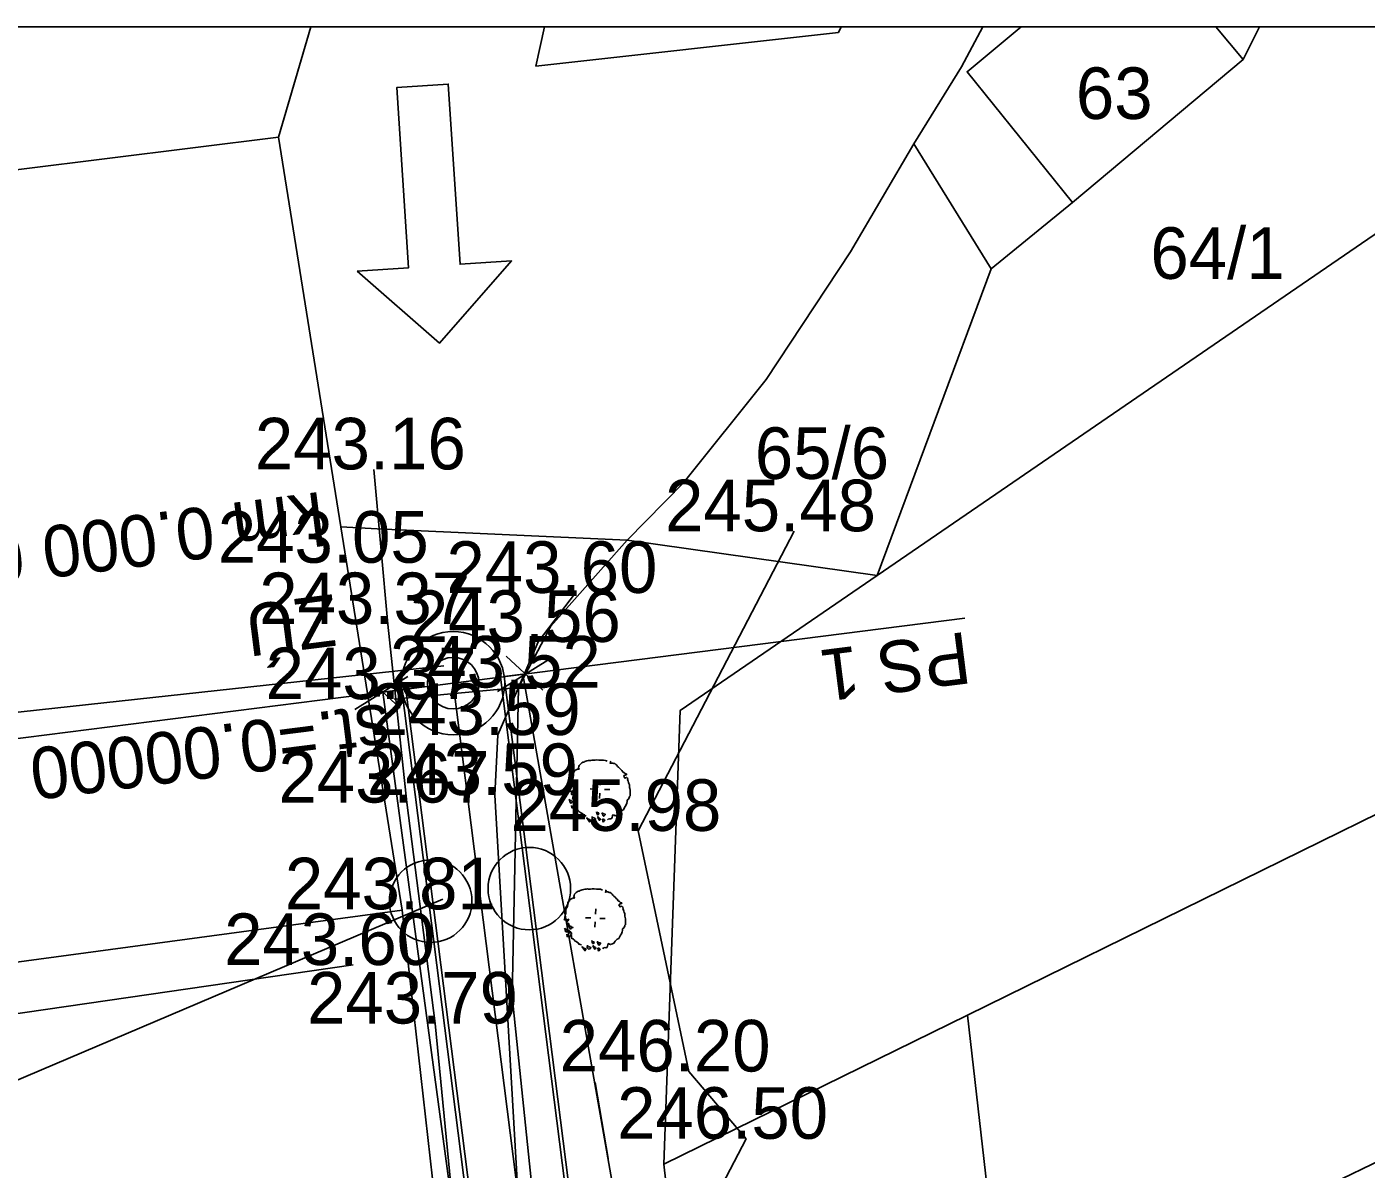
# Model space of a CAD drawing. Extents: x -601754 to -601440, y -1201912 to -1200862.
# Drawn here: x -601652.4 to -601600.5, y -1200906.7 to -1200862.4 of the extents above; entities that cross this region are included whole.
import ezdxf

# ---------------------------------------------------------------- set-up
doc = ezdxf.new("R2010")
doc.units = 0
for name, color, linetype in [('Hranice parcel', 7, 'Continuous'), ('Parcelní čísla', 7, 'Continuous'), ('u_hrany', 7, 'Continuous'), ('u_krizky', 7, 'Continuous'), ('u_návrh', 7, 'Continuous'), ('u_osa', 7, 'Continuous'), ('u_popis', 7, 'Continuous'), ('u_pricne_cesta', 7, 'Continuous'), ('u_prijezd', 7, 'Continuous'), ('u_S0 02', 7, 'Continuous'), ('u_sklony', 7, 'Continuous'), ('u_staniceni', 7, 'Continuous'), ('u_terénní úpravy', 7, 'Continuous'), ('u_vysadba_SO_101', 7, 'Continuous'), ('u_vyska', 7, 'Continuous'), ('x_rám', 7, 'Continuous')]:
    doc.layers.add(name, color=color, linetype=linetype)

msp = doc.modelspace()

# ---------------------------------------------------------------- linework, layer by layer
at = {"layer": 'Hranice parcel'}
for p, q in [((-601605.22, -1200863.63), (-601604.594, -1200862.355)), ((-601611.84, -1200869.17), (-601605.22, -1200863.63)), ((-601642.63, -1200866.63), (-601640.22, -1200881.75)), ((-601618, -1200866.89), (-601615, -1200871.74)), ((-601615, -1200871.74), (-601611.84, -1200869.17)), ((-601619.42, -1200883.64), (-601615, -1200871.74)), ((-601640.22, -1200881.75), (-601637.83, -1200896.61)), ((-601629.11, -1200882.26), (-601619.42, -1200883.64)), ((-601681.14, -1200902.44), (-601637.83, -1200896.61)), ((-601637.83, -1200896.61), (-601635.81, -1200914.55)), ((-601627.69, -1200906.47), (-601615.91, -1200900.68)), ((-601615.91, -1200900.68), (-601614.48, -1200913.35)), ((-601627.69, -1200906.47), (-601626.27, -1200919.05))]:
    msp.add_line(p, q, dxfattribs=at)
for points in [[(-601641.381, -1200862.355), (-601642.63, -1200866.63)], [(-601620.81, -1200862.355), (-601620.92, -1200862.58), (-601632.65, -1200863.88), (-601632.31, -1200862.355)], [(-601618, -1200866.89), (-601616.15, -1200863.91), (-601615.318, -1200862.355)], [(-601613.837, -1200862.355), (-601615.93, -1200864.1), (-601611.84, -1200869.17)], [(-601615.91, -1200900.68), (-601566.47, -1200876.38), (-601536.982, -1200862.355)], [(-601514.155, -1200862.355), (-601515.21, -1200862.87), (-601539.23, -1200875.18), (-601559.8, -1200886.93), (-601614.48, -1200913.35)], [(-601605.22, -1200863.63), (-601606.283, -1200862.355)], [(-601594.19, -1200866.34), (-601602.69, -1200872.17), (-601619.42, -1200883.64)], [(-601642.63, -1200866.63), (-601692.48, -1200872.84), (-601687.91, -1200898.84)], [(-601629.11, -1200882.26), (-601626.94, -1200880.05), (-601623.72, -1200876.03), (-601620.45, -1200871.08), (-601618, -1200866.89)], [(-601640.22, -1200881.75), (-601638.8, -1200881.82), (-601629.11, -1200882.26)], [(-601611.28, -1200963.08), (-601614.07, -1200959.31), (-601621.9, -1200946.57), (-601626.39, -1200937.08), (-601630.02, -1200926.25), (-601631.65, -1200918.55), (-601633.57, -1200899.96), (-601633.33, -1200887.98), (-601632.07, -1200885.6), (-601629.11, -1200882.26)], [(-601619.42, -1200883.64), (-601627.05, -1200888.87), (-601627.69, -1200906.47)]]:
    msp.add_lwpolyline(points, dxfattribs=at)
at = {"layer": 'u_hrany'}
for points in [[(-601638.94, -1200879.52), (-601638.39, -1200885.52), (-601637.65, -1200892.44)], [(-601624.49, -1200905.48), (-601626.72, -1200902.87), (-601628.68, -1200893.54), (-601622.63, -1200881.92)], [(-601633.33, -1200887.98), (-601632.56, -1200886.21), (-601631.11, -1200884.31)], [(-601633.33, -1200887.98), (-601638.14, -1200888.43)], [(-601634.24, -1200892.15), (-601634.13, -1200889.82), (-601633.33, -1200887.98)], [(-601637.65, -1200892.44), (-601636.56, -1200901.01), (-601634.78, -1200919.25), (-601632.6, -1200928.32), (-601629.33, -1200937.82), (-601624.51, -1200947.91), (-601616.86, -1200961.13), (-601606.97, -1200974.25), (-601596.82, -1200985.88), (-601582.46, -1201002.22), (-601574.49, -1201012.64), (-601569.33, -1201022.81), (-601566.79, -1201038.25), (-601566.21, -1201048.21)], [(-601634.24, -1200892.15), (-601633.27, -1200908.88), (-601626.53, -1200909.37)], [(-601654.08, -1200900.82), (-601639.73, -1200898.74)], [(-601626.53, -1200909.37), (-601624.49, -1200905.48)]]:
    msp.add_lwpolyline(points, dxfattribs=at)
at = {"layer": 'u_krizky'}
for p, q in [((-601632.084, -1200886.85), (-601634.137, -1200888.13)), ((-601632.377, -1200888.077), (-601633.804, -1200886.757)), ((-601637.615, -1200887.553), (-601639.668, -1200888.833)), ((-601637.908, -1200888.779), (-601639.335, -1200887.46))]:
    msp.add_line(p, q, dxfattribs=at)
at = {"layer": 'u_návrh'}
for points in [[(-601634.025, -1200887.577), (-601630.185, -1200917.812), (-601628.225, -1200928.505), (-601625.119, -1200938.871), (-601620.896, -1200948.834), (-601615.607, -1200958.274), (-601609.285, -1200967.119), (-601584.73, -1200997.764)], [(-601633.876, -1200887.558), (-601630.036, -1200917.789), (-601628.079, -1200928.47), (-601624.978, -1200938.82), (-601620.761, -1200948.768), (-601615.48, -1200958.194), (-601609.165, -1200967.028), (-601578.723, -1201005.021)], [(-601637.844, -1200888.062), (-601633.991, -1200918.402), (-601631.974, -1200929.408), (-601628.747, -1200940.179), (-601624.358, -1200950.531), (-601618.862, -1200960.341), (-601612.355, -1200969.444), (-601581.832, -1201007.537)], [(-601637.695, -1200888.043), (-601633.842, -1200918.379), (-601631.828, -1200929.372), (-601628.605, -1200940.128), (-601624.223, -1200950.465), (-601618.735, -1200960.26), (-601612.236, -1200969.353), (-601587.617, -1201000.078)]]:
    msp.add_lwpolyline(points, dxfattribs=at)
at = {"layer": 'u_osa'}
msp.add_lwpolyline([(-601635.86, -1200887.81), (-601632.013, -1200918.095), (-601630.026, -1200928.939), (-601626.862, -1200939.5), (-601622.56, -1200949.65), (-601617.171, -1200959.267), (-601610.76, -1200968.236), (-601578.672, -1201008.284), (-601575.031, -1201013.469), (-601572.075, -1201019.074), (-601569.852, -1201025.007), (-601568.398, -1201031.174), (-601566.15, -1201044.408), (-601565.576, -1201049.148), (-601565.456, -1201053.922), (-601565.793, -1201058.685), (-601566.228, -1201062.343), (-601567.198, -1201067.854), (-601568.778, -1201073.221), (-601570.948, -1201078.378), (-601573.681, -1201083.261), (-601575.226, -1201085.692), (-601578.132, -1201090.011)], dxfattribs=at)
at = {"layer": 'u_popis'}
msp.add_line((-601636.264, -1200896.19), (-601666.299, -1200908.964), dxfattribs=at)
for centre in [(-601632.904, -1200895.778), (-601636.729, -1200896.264)]:
    msp.add_circle(centre, 1.6, dxfattribs=at)
at = {"layer": 'u_pricne_cesta'}
msp.add_lwpolyline([(-601616.019, -1200885.29), (-601635.86, -1200887.81), (-601638.582, -1200888.156), (-601655.701, -1200890.33)], dxfattribs=at)
at = {"layer": 'u_prijezd'}
msp.add_lwpolyline([(-601639.58, -1200871.829), (-601636.388, -1200874.624), (-601633.593, -1200871.432), (-601635.588, -1200871.564), (-601636.051, -1200864.58), (-601638.047, -1200864.712), (-601637.584, -1200871.697), (-601639.58, -1200871.829)], dxfattribs=at)
at = {"layer": 'u_S0 02'}
msp.add_lwpolyline([(-601674.6, -1200939.813), (-601674.6, -1200891.308), (-601636.214, -1200887.14)], dxfattribs=at)
at = {"layer": 'u_sklony'}
msp.add_line((-601630.346, -1200903.301), (-601629.843, -1200906.247), dxfattribs=at)
at = {"layer": 'u_staniceni'}
for radius in [2, 1]:
    msp.add_circle((-601635.86, -1200887.81), radius, dxfattribs=at)
at = {"layer": 'u_terénní úpravy'}
for p, q in [((-601633.16, -1200887.467), (-601633.876, -1200887.558)), ((-601638.582, -1200888.156), (-601637.844, -1200888.062))]:
    msp.add_line(p, q, dxfattribs=at)
for points in [[(-601633.16, -1200887.467), (-601629.246, -1200909.745), (-601626.671, -1200923.479)], [(-601638.582, -1200888.156), (-601634.493, -1200918.503), (-601632.607, -1200929.56), (-601631.638, -1200933.524), (-601630.127, -1200940.76), (-601625.442, -1200954.325), (-601625.442, -1200954.325), (-601620.62, -1200961.457), (-601614.291, -1200970.175), (-601602.86, -1200984.783)]]:
    msp.add_lwpolyline(points, dxfattribs=at)
at = {"layer": 'u_vysadba_SO_101'}
for points in [[(-601631.154, -1200891.227), (-601631.152, -1200891.198), (-601631.093, -1200891.172), (-601631.063, -1200891.159), (-601631.033, -1200891.146), (-601631.003, -1200891.147), (-601630.974, -1200891.149), (-601630.987, -1200891.119), (-601631, -1200891.089), (-601630.983, -1200891.046), (-601630.966, -1200891.003), (-601630.935, -1200890.96), (-601630.904, -1200890.933), (-601630.873, -1200890.905), (-601630.828, -1200890.878), (-601630.784, -1200890.88), (-601630.754, -1200890.853), (-601630.679, -1200890.827), (-601630.62, -1200890.816), (-601630.575, -1200890.804), (-601630.517, -1200890.807), (-601630.472, -1200890.794), (-601630.428, -1200890.797), (-601630.355, -1200890.801), (-601630.282, -1200890.79), (-601630.209, -1200890.794), (-601630.121, -1200890.798), (-601630.033, -1200890.803), (-601629.96, -1200890.807), (-601629.917, -1200890.824), (-601629.889, -1200890.84)], [(-601629.742, -1200890.833), (-601629.758, -1200890.861), (-601629.76, -1200890.891), (-601629.776, -1200890.919), (-601629.731, -1200890.907), (-601629.702, -1200890.908), (-601629.673, -1200890.91), (-601629.63, -1200890.927), (-601629.586, -1200890.929), (-601629.544, -1200890.961), (-601629.516, -1200890.991), (-601629.489, -1200891.037), (-601629.447, -1200891.068), (-601629.391, -1200891.115), (-601629.35, -1200891.161), (-601629.322, -1200891.192), (-601629.281, -1200891.253), (-601629.224, -1200891.285), (-601629.182, -1200891.317), (-601629.139, -1200891.333), (-601629.141, -1200891.363)], [(-601631.154, -1200891.227), (-601631.155, -1200891.242), (-601631.201, -1200891.283), (-601631.232, -1200891.311), (-601631.234, -1200891.355), (-601631.236, -1200891.398), (-601631.239, -1200891.457), (-601631.256, -1200891.5), (-601631.272, -1200891.528), (-601631.289, -1200891.557), (-601631.306, -1200891.614), (-601631.308, -1200891.643), (-601631.311, -1200891.702), (-601631.313, -1200891.746), (-601631.315, -1200891.775), (-601631.333, -1200891.847), (-601631.35, -1200891.89), (-601631.352, -1200891.934), (-601631.369, -1200891.962), (-601631.356, -1200891.992), (-601631.313, -1200892.009), (-601631.223, -1200891.985), (-601631.193, -1200891.972), (-601631.226, -1200892.029), (-601631.256, -1200892.056), (-601631.273, -1200892.085), (-601631.275, -1200892.128), (-601631.246, -1200892.13), (-601631.202, -1200892.132), (-601631.189, -1200892.162), (-601631.206, -1200892.205), (-601631.222, -1200892.234), (-601631.224, -1200892.278), (-601631.226, -1200892.321)], [(-601629.141, -1200891.363), (-601629.185, -1200891.375), (-601629.23, -1200891.387), (-601629.246, -1200891.416), (-601629.233, -1200891.446), (-601629.206, -1200891.491), (-601629.176, -1200891.478), (-601629.131, -1200891.466), (-601629.104, -1200891.496), (-601629.091, -1200891.526), (-601629.092, -1200891.556), (-601629.066, -1200891.616), (-601629.054, -1200891.66), (-601629.041, -1200891.705), (-601629.015, -1200891.75), (-601629.016, -1200891.779), (-601629.018, -1200891.823), (-601629.02, -1200891.852), (-601629.008, -1200891.897), (-601628.996, -1200891.956), (-601628.999, -1200892.014), (-601628.988, -1200892.074), (-601628.989, -1200892.103), (-601628.991, -1200892.132), (-601628.993, -1200892.176), (-601629.024, -1200892.203), (-601629.025, -1200892.233), (-601629.042, -1200892.276), (-601629.058, -1200892.304), (-601629.105, -1200892.346), (-601629.108, -1200892.404), (-601629.125, -1200892.462), (-601629.144, -1200892.534), (-601629.191, -1200892.59), (-601629.224, -1200892.661), (-601629.256, -1200892.718), (-601629.316, -1200892.744), (-601629.347, -1200892.772), (-601629.393, -1200892.814), (-601629.424, -1200892.856), (-601629.441, -1200892.899), (-601629.501, -1200892.925), (-601629.546, -1200892.937), (-601629.576, -1200892.95), (-601629.619, -1200892.933), (-601629.662, -1200892.917), (-601629.679, -1200892.96), (-601629.696, -1200893.017), (-601629.713, -1200893.06), (-601629.758, -1200893.073), (-601629.802, -1200893.07)], [(-601630.338, -1200891.92), (-601630.543, -1200891.909)], [(-601630.155, -1200891.769), (-601630.144, -1200891.564)], [(-601629.988, -1200891.938), (-601629.783, -1200891.935)], [(-601631.358, -1200892.314), (-601631.345, -1200892.344), (-601631.333, -1200892.389), (-601631.32, -1200892.419), (-601631.321, -1200892.448), (-601631.293, -1200892.464), (-601631.262, -1200892.437), (-601631.216, -1200892.395), (-601631.245, -1200892.394), (-601631.287, -1200892.362), (-601631.33, -1200892.345)], [(-601631.2, -1200892.381), (-601631.159, -1200892.427), (-601631.117, -1200892.474), (-601631.075, -1200892.505)], [(-601631.075, -1200892.505), (-601631.104, -1200892.504), (-601631.134, -1200892.502), (-601631.163, -1200892.5), (-601631.176, -1200892.47), (-601631.174, -1200892.441), (-601631.187, -1200892.411)], [(-601631.176, -1200892.192), (-601631.178, -1200892.236), (-601631.165, -1200892.266), (-601631.153, -1200892.311), (-601631.14, -1200892.341), (-601631.11, -1200892.342), (-601631.094, -1200892.314), (-601631.034, -1200892.288), (-601631.077, -1200892.271), (-601631.106, -1200892.255), (-601631.163, -1200892.222)], [(-601630.171, -1200892.075), (-601630.182, -1200892.28)], [(-601631.268, -1200892.553), (-601631.258, -1200892.642), (-601631.214, -1200892.644), (-601631.185, -1200892.646), (-601631.14, -1200892.633), (-601631.198, -1200892.616), (-601631.242, -1200892.613), (-601631.255, -1200892.583)], [(-601630.704, -1200892.964), (-601630.747, -1200892.947), (-601630.775, -1200892.931), (-601630.805, -1200892.929), (-601630.832, -1200892.884), (-601630.86, -1200892.868), (-601630.902, -1200892.836), (-601630.945, -1200892.819), (-601630.987, -1200892.773), (-601631.014, -1200892.743), (-601631.086, -1200892.709), (-601631.084, -1200892.666), (-601631.081, -1200892.622), (-601631.094, -1200892.592), (-601631.123, -1200892.576), (-601631.091, -1200892.533), (-601631.062, -1200892.535)], [(-601630.3, -1200892.795), (-601630.289, -1200892.869), (-601630.262, -1200892.914), (-601630.218, -1200892.902), (-601630.216, -1200892.873), (-601630.214, -1200892.843), (-601630.257, -1200892.826), (-601630.286, -1200892.81)], [(-601630.265, -1200892.972), (-601630.181, -1200893.05), (-601630.153, -1200893.066), (-601630.14, -1200893.096), (-601630.171, -1200893.124), (-601630.2, -1200893.122), (-601630.213, -1200893.092), (-601630.24, -1200893.047), (-601630.268, -1200893.016)], [(-601630.097, -1200892.835), (-601630.071, -1200892.895), (-601630.058, -1200892.939), (-601630.031, -1200892.97), (-601630.001, -1200892.957), (-601629.969, -1200892.915), (-601629.968, -1200892.886), (-601630.012, -1200892.883), (-601630.04, -1200892.867), (-601630.068, -1200892.851), (-601630.098, -1200892.85)], [(-601630.693, -1200893.023), (-601630.596, -1200893.145), (-601630.57, -1200893.191), (-601630.538, -1200893.148), (-601630.537, -1200893.119), (-601630.565, -1200893.103), (-601630.608, -1200893.086), (-601630.636, -1200893.07), (-601630.665, -1200893.054)], [(-601630.47, -1200892.976), (-601630.474, -1200893.049), (-601630.462, -1200893.094), (-601630.434, -1200893.125), (-601630.375, -1200893.113), (-601630.344, -1200893.085), (-601630.357, -1200893.055), (-601630.4, -1200893.039), (-601630.444, -1200893.022)], [(-601630.066, -1200893.086), (-601630.055, -1200893.159), (-601630.042, -1200893.189), (-601630.012, -1200893.176), (-601629.981, -1200893.134), (-601630.009, -1200893.103), (-601630.037, -1200893.087), (-601630.066, -1200893.086)], [(-601629.802, -1200893.07), (-601629.846, -1200893.082), (-601629.877, -1200893.11)], [(-601631.336, -1200896.224), (-601631.334, -1200896.194), (-601631.274, -1200896.168), (-601631.244, -1200896.155), (-601631.214, -1200896.142), (-601631.185, -1200896.144), (-601631.156, -1200896.145), (-601631.169, -1200896.115), (-601631.182, -1200896.085), (-601631.165, -1200896.042), (-601631.148, -1200895.999), (-601631.117, -1200895.957), (-601631.086, -1200895.929), (-601631.055, -1200895.902), (-601631.01, -1200895.875), (-601630.966, -1200895.877), (-601630.935, -1200895.849), (-601630.861, -1200895.824), (-601630.802, -1200895.813), (-601630.757, -1200895.8), (-601630.699, -1200895.803), (-601630.654, -1200895.791), (-601630.61, -1200895.793), (-601630.537, -1200895.797), (-601630.463, -1200895.787), (-601630.39, -1200895.79), (-601630.303, -1200895.795), (-601630.215, -1200895.8), (-601630.142, -1200895.804), (-601630.099, -1200895.82), (-601630.071, -1200895.837)], [(-601629.924, -1200895.83), (-601629.94, -1200895.858), (-601629.942, -1200895.887), (-601629.958, -1200895.916), (-601629.913, -1200895.903), (-601629.884, -1200895.905), (-601629.855, -1200895.907), (-601629.812, -1200895.923), (-601629.768, -1200895.926), (-601629.726, -1200895.957), (-601629.698, -1200895.988), (-601629.671, -1200896.033), (-601629.629, -1200896.065), (-601629.573, -1200896.112), (-601629.531, -1200896.158), (-601629.504, -1200896.189), (-601629.463, -1200896.249), (-601629.406, -1200896.282), (-601629.364, -1200896.313), (-601629.321, -1200896.33), (-601629.322, -1200896.359)], [(-601631.336, -1200896.224), (-601631.337, -1200896.238), (-601631.383, -1200896.28), (-601631.413, -1200896.307), (-601631.416, -1200896.351), (-601631.418, -1200896.395), (-601631.421, -1200896.453), (-601631.438, -1200896.496), (-601631.454, -1200896.525), (-601631.47, -1200896.553), (-601631.488, -1200896.611), (-601631.49, -1200896.64), (-601631.493, -1200896.699), (-601631.495, -1200896.742), (-601631.496, -1200896.772), (-601631.515, -1200896.844), (-601631.532, -1200896.887), (-601631.534, -1200896.931), (-601631.55, -1200896.959), (-601631.537, -1200896.989), (-601631.494, -1200897.006), (-601631.405, -1200896.981), (-601631.375, -1200896.968), (-601631.407, -1200897.025), (-601631.438, -1200897.053), (-601631.454, -1200897.081), (-601631.457, -1200897.125), (-601631.427, -1200897.127), (-601631.384, -1200897.129), (-601631.371, -1200897.159), (-601631.387, -1200897.202), (-601631.404, -1200897.23), (-601631.406, -1200897.274), (-601631.408, -1200897.318)], [(-601630.336, -1200896.765), (-601630.325, -1200896.561)], [(-601629.322, -1200896.359), (-601629.367, -1200896.372), (-601629.411, -1200896.384), (-601629.428, -1200896.412), (-601629.414, -1200896.442), (-601629.388, -1200896.488), (-601629.358, -1200896.475), (-601629.313, -1200896.462), (-601629.285, -1200896.493), (-601629.272, -1200896.523), (-601629.274, -1200896.552), (-601629.248, -1200896.612), (-601629.235, -1200896.657), (-601629.223, -1200896.701), (-601629.196, -1200896.747), (-601629.198, -1200896.776), (-601629.2, -1200896.82), (-601629.202, -1200896.849), (-601629.189, -1200896.893), (-601629.178, -1200896.953), (-601629.181, -1200897.011), (-601629.169, -1200897.07), (-601629.171, -1200897.099), (-601629.173, -1200897.129), (-601629.175, -1200897.172), (-601629.206, -1200897.2), (-601629.207, -1200897.229), (-601629.224, -1200897.272), (-601629.24, -1200897.301), (-601629.286, -1200897.342), (-601629.289, -1200897.401), (-601629.307, -1200897.458), (-601629.326, -1200897.531), (-601629.372, -1200897.587), (-601629.405, -1200897.658), (-601629.438, -1200897.715), (-601629.498, -1200897.741), (-601629.528, -1200897.769), (-601629.575, -1200897.81), (-601629.606, -1200897.853), (-601629.623, -1200897.896), (-601629.683, -1200897.922), (-601629.728, -1200897.934), (-601629.758, -1200897.947), (-601629.801, -1200897.93), (-601629.844, -1200897.913), (-601629.861, -1200897.956), (-601629.878, -1200898.014), (-601629.895, -1200898.057), (-601629.94, -1200898.069), (-601629.983, -1200898.067)], [(-601630.52, -1200896.917), (-601630.724, -1200896.906)], [(-601630.352, -1200897.072), (-601630.363, -1200897.276)], [(-601630.169, -1200896.935), (-601629.964, -1200896.931)], [(-601631.54, -1200897.311), (-601631.527, -1200897.341), (-601631.514, -1200897.386), (-601631.501, -1200897.416), (-601631.503, -1200897.445), (-601631.474, -1200897.461), (-601631.444, -1200897.433), (-601631.397, -1200897.392), (-601631.427, -1200897.39), (-601631.469, -1200897.359), (-601631.512, -1200897.342)], [(-601631.45, -1200897.55), (-601631.44, -1200897.639), (-601631.396, -1200897.641), (-601631.367, -1200897.642), (-601631.322, -1200897.63), (-601631.38, -1200897.612), (-601631.424, -1200897.61), (-601631.437, -1200897.58)], [(-601631.382, -1200897.378), (-601631.341, -1200897.424), (-601631.299, -1200897.47), (-601631.257, -1200897.502)], [(-601631.257, -1200897.502), (-601631.286, -1200897.5), (-601631.315, -1200897.499), (-601631.344, -1200897.497), (-601631.358, -1200897.467), (-601631.356, -1200897.438), (-601631.369, -1200897.408)], [(-601631.357, -1200897.189), (-601631.36, -1200897.233), (-601631.347, -1200897.263), (-601631.334, -1200897.307), (-601631.321, -1200897.337), (-601631.292, -1200897.339), (-601631.276, -1200897.31), (-601631.216, -1200897.284), (-601631.259, -1200897.267), (-601631.288, -1200897.251), (-601631.344, -1200897.219)], [(-601630.886, -1200897.961), (-601630.929, -1200897.944), (-601630.957, -1200897.928), (-601630.986, -1200897.926), (-601631.013, -1200897.881), (-601631.042, -1200897.865), (-601631.084, -1200897.833), (-601631.127, -1200897.816), (-601631.169, -1200897.77), (-601631.196, -1200897.739), (-601631.268, -1200897.706), (-601631.265, -1200897.662), (-601631.263, -1200897.619), (-601631.276, -1200897.589), (-601631.304, -1200897.572), (-601631.273, -1200897.53), (-601631.244, -1200897.532)], [(-601630.874, -1200898.02), (-601630.778, -1200898.142), (-601630.751, -1200898.187), (-601630.72, -1200898.145), (-601630.718, -1200898.116), (-601630.747, -1200898.1), (-601630.79, -1200898.083), (-601630.818, -1200898.067), (-601630.847, -1200898.051)], [(-601630.652, -1200897.973), (-601630.656, -1200898.046), (-601630.644, -1200898.091), (-601630.616, -1200898.121), (-601630.557, -1200898.11), (-601630.526, -1200898.082), (-601630.539, -1200898.052), (-601630.582, -1200898.035), (-601630.625, -1200898.018)], [(-601630.481, -1200897.792), (-601630.471, -1200897.865), (-601630.444, -1200897.911), (-601630.399, -1200897.898), (-601630.398, -1200897.869), (-601630.396, -1200897.84), (-601630.439, -1200897.823), (-601630.468, -1200897.807)], [(-601630.447, -1200897.969), (-601630.363, -1200898.047), (-601630.335, -1200898.063), (-601630.322, -1200898.093), (-601630.352, -1200898.121), (-601630.382, -1200898.119), (-601630.395, -1200898.089), (-601630.422, -1200898.044), (-601630.449, -1200898.013)], [(-601630.279, -1200897.832), (-601630.252, -1200897.892), (-601630.24, -1200897.936), (-601630.212, -1200897.967), (-601630.183, -1200897.954), (-601630.151, -1200897.912), (-601630.149, -1200897.882), (-601630.193, -1200897.88), (-601630.222, -1200897.864), (-601630.25, -1200897.848), (-601630.279, -1200897.846)], [(-601630.248, -1200898.082), (-601630.237, -1200898.156), (-601630.224, -1200898.186), (-601630.194, -1200898.173), (-601630.163, -1200898.131), (-601630.19, -1200898.1), (-601630.219, -1200898.084), (-601630.248, -1200898.082)], [(-601629.983, -1200898.067), (-601630.028, -1200898.079), (-601630.059, -1200898.107)]]:
    msp.add_lwpolyline(points, dxfattribs=at)
at = {"layer": 'x_rám'}
msp.add_lwpolyline([(-601454.585, -1200862.355), (-601454.585, -1201912.355), (-601751.585, -1201912.355), (-601751.585, -1200862.355)], close=True, dxfattribs=at)

# ---------------------------------------------------------------- texts
at = {"layer": 'Parcelní čísla'}
for s, p in [('63', (-601611.71, -1200865.93)), ('64/1', (-601608.82, -1200872.13)), ('65/6', (-601624.16, -1200879.89))]:
    msp.add_text(s, height=2, dxfattribs=at).set_placement(p)
at = {"layer": 'u_popis'}
for s, p in [('km 0.000 00', (-601640.989, -1200880.382)), ('ZÚ', (-601640.484, -1200884.352))]:
    msp.add_text(s, height=2, rotation=187.2385, dxfattribs=at).set_placement(p)
at = {"layer": 'u_pricne_cesta'}
for s, p in [('PS 1', (-601615.953, -1200885.814)), ('st.=0.00000', (-601638.426, -1200888.596))]:
    msp.add_text(s, height=2, rotation=187.2385, dxfattribs=at).set_placement(p)
at = {"layer": 'u_vyska'}
for s, p in [('243.16', (-601643.548, -1200879.52)), ('245.48', (-601627.642, -1200881.92)), ('243.05', (-601644.985, -1200883.14)), ('243.60', (-601636.12, -1200884.31)), ('243.37', (-601643.379, -1200885.52)), ('243.56', (-601637.539, -1200886.21)), ('243.52', (-601638.314, -1200887.98)), ('243.37', (-601643.129, -1200888.43)), ('243.59', (-601639.09, -1200889.82)), ('243.59', (-601639.2, -1200892.15)), ('243.67', (-601642.634, -1200892.44)), ('245.98', (-601633.64, -1200893.54)), ('243.81', (-601642.385, -1200896.58)), ('243.60', (-601644.74, -1200898.74)), ('243.79', (-601641.525, -1200901.01)), ('246.20', (-601631.73, -1200902.87)), ('246.50', (-601629.5, -1200905.48))]:
    msp.add_text(s, height=2, dxfattribs=at).set_placement(p)

doc.saveas('drawing.dxf')
